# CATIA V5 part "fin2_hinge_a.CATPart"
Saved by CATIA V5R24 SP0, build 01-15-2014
Part number: Hinge A
Bounding box of the stored display mesh (mm): x -3.719 to 3.719, y -3.747 to 3.747, z -3.875 to 3.875
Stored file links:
  G:\내 드라이브\04_WORK\00_LECTURE\CAD2020\exam\fin2_hinge_a.CATPart
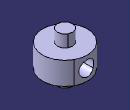
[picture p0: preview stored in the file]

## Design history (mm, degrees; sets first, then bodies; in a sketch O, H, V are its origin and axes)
Body1 (main body)
  Sketch1 on yz-plane, origin (0, 0, 0), H (0, 1, 0), V (0, 0, 1)
    axis line L1 (0, 7.3226) -> (0, -11.8388)
    point P1 (0, 7.3226)
    point P3 (0, 3.875)
    line L2 (0, 3.875) -> (-1.25, 3.875)
    line L3 (-1.25, 3.875) -> (-1.25, 1.875)
    line L4 (-1.25, 1.875) -> (-3.75, 1.875)
    line L5 (-3.75, 1.875) -> (-3.75, -1.875)
    line L6 (-3.75, -1.875) -> (-1.25, -1.875)
    point P8 (-1.25, -1.875)
    line L7 (-1.25, -1.875) -> (-1.25, -3.875)
    line L8 (-1.25, -3.875) -> (0, -3.875)
    point P10 (0, -3.875)
    distance L5 P3 = 3.75
    distance P10 L5 = 3.75
    distance L3 P3 = 1.25
    distance L4 L2 = 2
    distance L8 L6 = 2
    distance L6 L4 = 3.75
    coincidence: P1 V, P8 L3, P3 V
    horizontal: L2 H, L4 H, L6 H, L8 H
    vertical: L3 V, L5 V, L7 V, L1 V
    symmetry: L8 L2 H
  Shaft1: profile Sketch1, axis Sketch1.L1, angle 360
  Sketch2 on zx-plane, origin (-0.4607, 0, -0.6327), H (1, 0, 0), V (0, 0, -1)
    point P1 (0.4607, -0.6327)
    reference intersected line E1 through (0, -0.6327) direction (1, 0) from xy-plane
    reference intersected line E2 through (0.4607, 0) direction (0, 1) from yz-plane
    coincidence: P1 E1, P1 E2
  Hole1: placed by Sketch2, at (0, 0, 0) direction (0, -1, 0), diameter 2.5, through (limit type 3)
